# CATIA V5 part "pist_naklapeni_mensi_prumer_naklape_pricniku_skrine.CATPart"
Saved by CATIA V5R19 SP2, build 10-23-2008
Part number: pist_naklapeni_mensi_prumer_naklape_pricniku_skrine
Bounding box of the stored display mesh (mm): x -50 to 50, y -55 to 55, z 0 to 394.812
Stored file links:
  C:\Users\Martiin\Desktop\9.semestr\Projekt-diplomka\3D model\pist_naklapeni_mensi_prumer_naklape_pricniku_skrine.CATPart
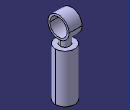
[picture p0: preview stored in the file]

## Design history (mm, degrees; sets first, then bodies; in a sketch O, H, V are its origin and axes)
Body1 (main body)
  Sketch1 on xy-plane, origin (0, 0, 0), H (1, 0, 0), V (0, 1, 0)
    circle A1 centre (0, 0) radius 50
    radius A1 = 50
  Pad1: profile Sketch1, direction (0, 0, 1), length 250
  Sketch2 on yz-plane, origin (0, 0, 0), H (0, 1, 0), V (0, 0, 1)
    circle A1 centre (0, 340) radius 45
    point P1 (0, 340)
    circle A2 centre (0, 340) radius 55
    reference projected line E1 (-35, 250) -> (35, 250) from edge [face of Pad1 from Sketch1.A1 | end face of Pad1]
    distance P1 E1 = 90
    radius A2 = 55
    radius A1 = 45
    coincidence: P1 V
    concentricity: A2 A1
  Pad2: profile Sketch2, direction (1, 0, 0), length 34, mirrored extent
  Sketch3 on end face of Pad1, origin (0, 0, 250), H (1, 0, 0), V (0, 1, 0)
    circle A1 centre (0, 0) radius 25
    radius A1 = 25
  Pad3: profile Sketch3, direction (0, 0, 1), up to the existing solid (limit type 2)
